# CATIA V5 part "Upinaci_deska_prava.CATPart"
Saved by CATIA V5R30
Part number: Upinaci_deska_prava
Definition: F 10_346446_36_1730_1
Nomenclature: F 10_346446_36_1730_1
Source: Unknown
Description: PART--DESC
Bounding box of the stored display mesh (mm): x -223 to 223, y -198 to 198, z 96.7 to 132.7
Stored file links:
  E:\Bakalarka\Model\Forma_v7\Upinaci_deska_prava.CATPart
  E:\Bakalarka\Model\Forma_v7\Vstrikovaci_cast.CATProduct
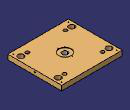
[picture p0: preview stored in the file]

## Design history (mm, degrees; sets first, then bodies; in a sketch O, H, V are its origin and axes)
Body1 "MANIFOLD_SOLID_BREP #4139" (main body)
  Solid1: solid without history
  Body2 "Result of TapHole"
    Solid2: linked copy from another document
  Assemble1 "TapHoleCapScrew_E1200_5.1": tool Body2
  Body3 "Result of TapHole"
    Solid3: linked copy from another document
  Assemble2 "TapHoleCapScrew_E1200_5.2": tool Body3
  Body4 "Result of TapHole"
    Solid4: linked copy from another document
  Assemble3 "TapHoleCountersunkScrew_E1220_5.1": tool Body4
  Body5 "Result of TapHole"
    Solid5: linked copy from another document
  Assemble4 "TapHoleCountersunkScrew_E1220_5.2": tool Body5
  Body6 "Result of TapHole"
    Solid6: linked copy from another document
  Assemble5 "TapHoleCountersunkScrew_E1220_5.3": tool Body6
  Body7 "Result of TapHole"
    Solid7: linked copy from another document
  Assemble6 "TapHoleCountersunkScrew_E1220_5.4": tool Body7
  DatumCurve1 to DatumCurve5
  DatumSurface1
  Sketch1 on face of Solid1, origin (0, 0, 128.7), H (1, 0, 0), V (0, 1, 0)
    projected arc E1 centre (0, 0) radius 19.55 from (19.55, 0) to (-19.55, 0) ccw from edge of DatumCurve3
    projected arc E2 centre (0, 0) radius 19.55 from (-19.55, 0) to (19.55, 0) ccw from edge of DatumCurve4
  Pocket1: profile Sketch1, direction (0, 0, -1), through (limit type 6)
  DatumCurve6
  DatumSurface2
  DatumCurve7
  Sketch2 on face of Solid1, origin (223, 0, 0), H (0, 1, 0), V (0, 0, 1)
    reference projected arc E2 centre (0, 116.7) radius 14 from (-14, 116.7) to (14, 116.7) ccw from edge of DatumCurve7
    point P5 (0, 116.7)
    concentricity: P5 E2
  Sketch3 on face of Solid1, origin (223, 0, 116.7), H (0, 1, 0), V (0, 0, 1)
    point P1 (0, 0)
    reference projected point E1 (0, 0) from Sketch2.P5
    coincidence: E1 P1
  Hole1: placed by Sketch3, at (223, 0, 116.7) direction (-1, 0, 0), diameter 10.106, depth 25, V-bottom angle 120, threaded "M12", thread diameter 12, thread depth 20, pitch 1.75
